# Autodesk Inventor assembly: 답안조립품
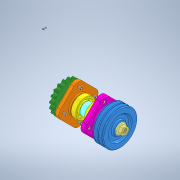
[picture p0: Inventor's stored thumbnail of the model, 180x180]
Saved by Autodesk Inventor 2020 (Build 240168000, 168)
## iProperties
Created: 2021-07
Part Number: 답안조립품
Document SubType Name: Assembly
Designer: Owner
Author: Owner
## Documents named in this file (15)
- C:\Users\Owner\Desktop\71070V1001\답안조립품.iam
- C:\Users\Owner\Desktop\71070V1001\본체.ipt
- C:\Users\Owner\Desktop\71070V1001\M16 너트.ipt
- C:\Users\Owner\Desktop\71070V1001\V-벨트풀리.ipt
- C:\Users\Owner\Desktop\71070V1001\멈춤나사 M4.ipt
- C:\Users\Owner\Desktop\71070V1001\베어링 6206.ipt
- C:\Users\Owner\Desktop\71070V1001\볼트 M6.ipt
- C:\Users\Owner\Desktop\71070V1001\부시.ipt
- C:\Users\Owner\Desktop\71070V1001\오일실 30x45x8.ipt
- C:\Users\Owner\Desktop\71070V1001\체인 스프로킷.ipt
- C:\Users\Owner\Desktop\71070V1001\축.ipt
- C:\Users\Owner\Desktop\71070V1001\커버A.ipt
- C:\Users\Owner\Desktop\71070V1001\커버B.ipt
- C:\Users\Owner\Desktop\71070V1001\키 6x6x18.ipt
- C:\Users\Owner\Desktop\71070V1001\키 6x6x20.ipt
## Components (3 placed, 2 different names)
1. M16 너트:1
2. V-벨트풀리:1
3. M16 너트:2
